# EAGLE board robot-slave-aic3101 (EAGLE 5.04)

Size 100 x 80 mm. Coordinates in mm from the lower left corner, seen from the top.
Outline: 0,0 100,0 100,80 0,80 0,0
Copper layers (1*16): Top 0.035mm / dielectric 1.5mm / Bottom 0.035mm
Design rules "default": minimum track width 10mil, minimum drill 24mil, track to track 8mil, track to pad 8mil, pad to pad 8mil, via to via 8mil, smd to smd 8mil, copper to edge 40mil, drill to drill 8mil, minimum pad ring 10mil, minimum via ring 8mil, stop-mask expansion 4mil, vias tented up to drill 0mil, thermal gap 10mil
Holes 2.8 mm at 3.81,3.81 95.25,3.81 95.25,76.2 3.81,76.2

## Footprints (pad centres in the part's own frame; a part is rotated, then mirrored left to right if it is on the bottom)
SCHMARTBOARD-VQFN32 = drill 0.5 pad 1.676 octagon: 1 -4.445,-15.24; 2 -3.175,-11.43; 3 -1.905,-15.24; 4 -0.635,-11.43; 5 0.635,-15.24; 6 1.905,-11.43; 7 3.175,-15.24; 8 4.445,-11.43; 9 10.795,-5.08; 10 14.605,-3.81; 11 10.795,-2.54; 12 14.605,-1.27; 13 10.795,0; 14 14.605,1.27; 15 10.795,2.54; 16 14.605,3.81; 17 4.445,11.43; 18 3.175,15.24; 19 1.905,11.43; 20 0.635,15.24; 21 -0.635,11.43; 22 -1.905,15.24; 23 -3.175,11.43; 24 -4.445,15.24; 25 -15.875,3.81; 26 -12.065,2.54; 27 -15.875,1.27; 28 -12.065,0; 29 -15.875,-1.27; 30 -12.065,-2.54; 31 -15.875,-3.81; 32 -12.065,-5.08
SAMTEC-10X2 = smd 0.74 x 2.92: 1 -6.358,-1.296; 2 -6.358,2.134; 3 -5.088,-1.296; 4 -5.088,2.134; 5 -3.818,-1.296; 6 -3.818,2.134; 7 -2.548,-1.296; 8 -2.548,2.134; 9 -1.278,-1.296; 10 -1.278,2.134; 11 -0.008,-1.296; 12 -0.008,2.134; 13 1.262,-1.296; 14 1.262,2.134; 15 2.532,-1.296; 16 2.532,2.134; 17 3.802,-1.296; 18 3.802,2.134; 19 5.072,-1.296; 20 5.072,2.134 | hole 0.508: -7.938,0.42; 6.66,0.42

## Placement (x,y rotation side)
CODEC  TLV320AIC3101  [SCHMARTBOARD-VQFN32]  25.4,22.86 0 top
JP1  SAMTEC-10X2  [SAMTEC-10X2]  43.18,59.69 270 bottom
JP2  SAMTEC-10X2  [SAMTEC-10X2]  12.7,59.69 270 bottom

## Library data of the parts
CODEC JP1 JP2 = trl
